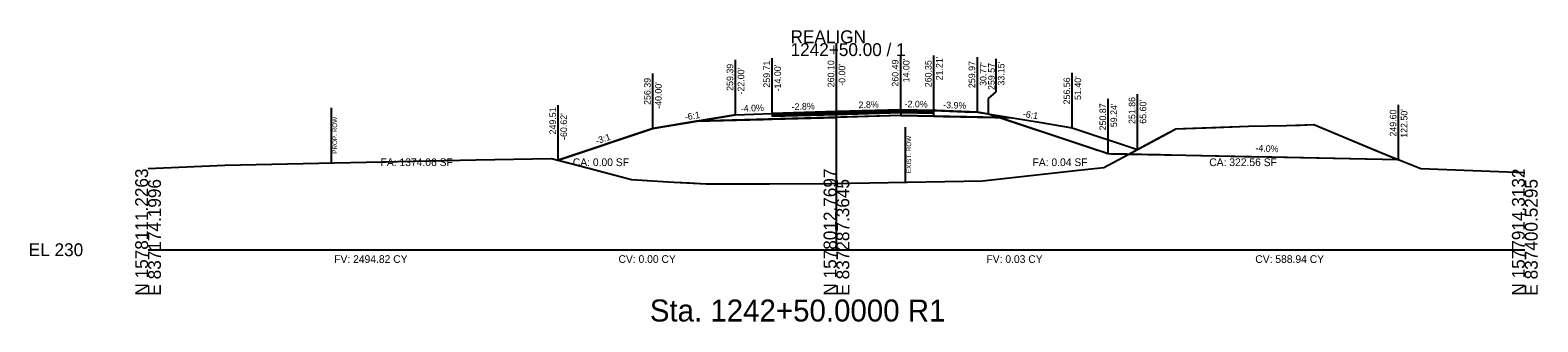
# Model space of a CAD drawing. Extents: x -26 to 6303, y -16 to 9563.
# Drawn here: x 1974.3 to 2302.8, y 2484.3 to 2547.8 of the extents above; entities that cross this region are included whole.
import ezdxf

# ---------------------------------------------------------------- set-up
doc = ezdxf.new("R2010")
doc.units = 0
for name, color, linetype in [('ASPHALT_19MM1', 7, 'Continuous'), ('ASPHALT_9_5MM1', 7, 'Continuous'), ('CONST_DCH', 7, 'Continuous'), ('CONST_LV3', 7, 'Continuous'), ('Draft_XS_Grid', 7, 'Continuous'), ('Draft_XS_Text', 7, 'Continuous'), ('DTM_P_FINISHED_GRADE', 7, 'Continuous'), ('DTM_P_FINISHED_GRADE2', 7, 'Continuous'), ('DTM_TEMP_DROP', 7, 'Continuous'), ('DTM_X_GROUND', 7, 'Continuous'), ('TRANS_EOP_PAVED', 7, 'Continuous'), ('TRANS_PAVED_SHOULDERS', 7, 'Continuous'), ('XS_CELL', 7, 'Continuous'), ('XS_M_SHAPES_EARTHWORK', 7, 'Continuous'), ('XS_P_ASPHALT', 7, 'Continuous'), ('XS_P_GROUND', 7, 'Continuous'), ('XS_P_ROW', 7, 'Continuous'), ('XS_P_SHOULDER', 7, 'Continuous'), ('XS_P_SUBGRADE_GRANULAR', 7, 'Continuous'), ('XS_P_TX_CLEARZONE', 7, 'Continuous'), ('XS_P_TX_FS_BS', 7, 'Continuous'), ('XS_SHEET_EW_TX_AREA', 7, 'Continuous'), ('XS_SHEET_EW_TX_VOLUME', 7, 'Continuous'), ('XS_X_ROW', 7, 'Continuous')]:
    doc.layers.add(name, color=color, linetype=linetype)

msp = doc.modelspace()

# ---------------------------------------------------------------- linework, layer by layer
at = {"layer": 'ASPHALT_19MM1'}
for points in [[(2136, 2529.37), (2136, 2529.1), (2150, 2529.49), (2150, 2529.49), (2164, 2529.89), (2164, 2529.89), (2164, 2530.16), (2164, 2530.16), (2164, 2530.16), (2150, 2529.77), (2150, 2529.77), (2136, 2529.37), (2136, 2529.37)], [(2164, 2530.16), (2164, 2529.89), (2164, 2529.89), (2171.21, 2529.74), (2171.21, 2530.01), (2164, 2530.16), (2164, 2530.16)]]:
    msp.add_lwpolyline(points, dxfattribs=at)
at = {"layer": 'ASPHALT_9_5MM1'}
for points in [[(2136, 2529.71), (2136, 2529.58), (2150, 2529.97), (2150, 2529.97), (2164, 2530.37), (2164, 2530.37), (2164, 2530.49), (2164, 2530.49), (2164, 2530.49), (2150, 2530.1), (2150, 2530.1), (2136, 2529.71), (2136, 2529.71)], [(2164, 2530.49), (2164, 2530.37), (2164, 2530.37), (2171.21, 2530.22), (2171.21, 2530.35), (2164, 2530.49), (2164, 2530.49)]]:
    msp.add_lwpolyline(points, dxfattribs=at)
at = {"layer": 'CONST_LV3'}
for points in [[(2171.21, 2530.35), (2171.21, 2530.35), (2164, 2530.49), (2164, 2530.49), (2150, 2530.1)], [(2164, 2530.49), (2164, 2529.22), (2164, 2529.22), (2171.21, 2529.07), (2171.21, 2530.35), (2164, 2530.49), (2164, 2530.49)], [(2180.71, 2529.97), (2180.71, 2529.97), (2173.67, 2530.25), (2173.67, 2530.25), (2171.78, 2530.32), (2171.78, 2530.32), (2171.21, 2530.35)], [(2119.53, 2527.98), (2110, 2526.39)]]:
    msp.add_lwpolyline(points, dxfattribs=at)
at = {"layer": 'DTM_P_FINISHED_GRADE'}
msp.add_lwpolyline([(2164, 2530.49), (2164, 2530.49), (2171.21, 2530.35)], dxfattribs=at)
at = {"layer": 'DTM_P_FINISHED_GRADE2'}
msp.add_lwpolyline([(2089.38, 2519.51), (2110, 2526.39), (2128, 2529.39), (2136, 2529.71), (2150, 2530.1), (2164, 2530.49), (2171.21, 2530.35), (2177.96, 2530.08), (2180.77, 2529.97)], dxfattribs=at)
at = {"layer": 'DTM_X_GROUND'}
msp.add_lwpolyline([(2000, 2517.66), (2016.7, 2518.4), (2071.45, 2519.57), (2087.88, 2519.91), (2095.75, 2517.83), (2105.32, 2515.27), (2114.55, 2514.74), (2121.62, 2514.35), (2121.89, 2514.36), (2148.98, 2514.4), (2181.82, 2514.99), (2202.74, 2517.35), (2208.26, 2517.94), (2221.97, 2525.27), (2223.99, 2526.35), (2225.61, 2526.4), (2239.79, 2526.89), (2248.07, 2527.1), (2254.04, 2527.25), (2267.88, 2521.46), (2277.32, 2517.67), (2300, 2516.79)], dxfattribs=at)
at = {"layer": 'TRANS_PAVED_SHOULDERS'}
for points in [[(2136, 2529.58), (2136, 2529.37), (2150, 2529.77), (2150, 2529.77), (2164, 2530.16), (2164, 2530.16), (2164, 2530.37), (2164, 2530.37), (2164, 2530.37), (2150, 2529.97), (2150, 2529.97), (2136, 2529.58), (2136, 2529.58)], [(2164, 2530.37), (2164, 2530.16), (2164, 2530.16), (2171.21, 2530.01), (2171.21, 2530.22), (2164, 2530.37), (2164, 2530.37)]]:
    msp.add_lwpolyline(points, dxfattribs=at)
at = {"layer": 'XS_CELL'}
for p, q in [((2150, 2500), (2150, 2545)), ((2000, 2500), (2150, 2500)), ((2150, 2500), (2300, 2500))]:
    msp.add_line(p, q, dxfattribs=at)
at = {"layer": 'XS_M_SHAPES_EARTHWORK'}
msp.add_lwpolyline([(2089.38, 2519.51), (2095.75, 2517.83), (2105.32, 2515.27), (2109.94, 2515.01), (2114.55, 2514.74), (2118.09, 2514.55), (2121.62, 2514.35), (2135.43, 2514.38), (2148.98, 2514.4), (2165.4, 2514.7), (2181.82, 2514.99), (2192.28, 2516.17), (2202.74, 2517.35), (2205.5, 2517.64), (2208.26, 2517.94), (2213.57, 2520.78), (2209.24, 2520.87), (2185.46, 2528.8), (2164, 2529.22), (2119.53, 2527.98), (2110, 2526.39)], close=True, dxfattribs=at)
at = {"layer": 'XS_P_ASPHALT'}
msp.add_lwpolyline([(2164, 2530.49), (2164, 2530.49), (2171.21, 2530.35)], dxfattribs=at)
at = {"layer": 'XS_P_GROUND'}
for points in [[(2209.24, 2520.87), (2209.24, 2520.87), (2209.01, 2520.95), (2208.99, 2520.95), (2208.98, 2520.95), (2208.98, 2520.95), (2208.98, 2520.95), (2208.87, 2520.99), (2208.86, 2521), (2208.41, 2521.15), (2207.04, 2521.6), (2207.04, 2521.6), (2207.02, 2521.61), (2207.01, 2521.61), (2207.01, 2521.61), (2206.89, 2521.65), (2206.89, 2521.65), (2206.47, 2521.79), (2206.47, 2521.79), (2205.24, 2522.2), (2205.24, 2522.2), (2183.15, 2529.57), (2183.15, 2529.57), (2183.15, 2529.57), (2180.82, 2529.95), (2180.82, 2529.95), (2180.71, 2529.97)], [(2180.77, 2529.97), (2194.15, 2527.76), (2201.4, 2526.56), (2215.6, 2521.86)], [(2128, 2529.39), (2110, 2526.39), (2089.38, 2519.51)], [(2240.08, 2520.25), (2239, 2520.27), (2239, 2520.27), (2222.96, 2520.59), (2222.96, 2520.59), (2222.96, 2520.59), (2221.57, 2520.62), (2221.57, 2520.62), (2220.6, 2520.64), (2220.59, 2520.64), (2220.59, 2520.64), (2220.54, 2520.64), (2220.54, 2520.64), (2220.47, 2520.64), (2220.44, 2520.64), (2220.44, 2520.64), (2219.04, 2520.67), (2219.04, 2520.67), (2218.12, 2520.69), (2218.11, 2520.69), (2218.11, 2520.69), (2218.07, 2520.69), (2218.07, 2520.69), (2218.01, 2520.69), (2218.01, 2520.69), (2217.96, 2520.69), (2217.96, 2520.69), (2216.53, 2520.72), (2216.53, 2520.72), (2215.69, 2520.74), (2215.68, 2520.74), (2215.68, 2520.74), (2215.65, 2520.74), (2215.65, 2520.74), (2215.61, 2520.74), (2215.61, 2520.74), (2215.53, 2520.74), (2214.02, 2520.77), (2214.02, 2520.77), (2213.34, 2520.78), (2213.34, 2520.78), (2213.32, 2520.79), (2213.3, 2520.79), (2213.2, 2520.79), (2213.2, 2520.79), (2211.4, 2520.82), (2211.4, 2520.82), (2211.1, 2520.83), (2211.1, 2520.83), (2211.09, 2520.83), (2211.08, 2520.83), (2211.05, 2520.83), (2210.96, 2520.83), (2210.96, 2520.83), (2209.98, 2520.85), (2209.98, 2520.85), (2209.95, 2520.85), (2209.93, 2520.85), (2209.24, 2520.87), (2209.24, 2520.87)], [(2272.5, 2519.6), (2244.84, 2520.15), (2240.47, 2520.24), (2240.08, 2520.25)]]:
    msp.add_lwpolyline(points, dxfattribs=at)
at = {"layer": 'XS_P_ROW'}
msp.add_line((2040, 2518.9), (2040, 2530.9), dxfattribs=at)
at = {"layer": 'XS_P_SHOULDER'}
for points in [[(2128, 2529.39), (2136, 2529.71), (2136, 2529.71)], [(2171.21, 2530.35), (2180.77, 2529.97)]]:
    msp.add_lwpolyline(points, dxfattribs=at)
at = {"layer": 'XS_P_SUBGRADE_GRANULAR'}
for points in [[(2119.53, 2527.98), (2134, 2528.38), (2134, 2528.38), (2136, 2528.44), (2136, 2528.44)], [(2136, 2528.44), (2150, 2528.83), (2150, 2528.83)], [(2164, 2529.22), (2164, 2529.22), (2150, 2528.83)], [(2164, 2529.22), (2164, 2529.22), (2171.21, 2529.07)], [(2171.21, 2529.07), (2173.23, 2529.04), (2188.2, 2528.74)]]:
    msp.add_lwpolyline(points, dxfattribs=at)
at = {"layer": 'XS_P_TX_CLEARZONE'}
for p, q in [((2128, 2529.39), (2128, 2541.39)), ((2136, 2529.71), (2136, 2541.71)), ((2150, 2530.1), (2150, 2542.1)), ((2164, 2530.49), (2164, 2542.49)), ((2171.21, 2530.35), (2171.21, 2542.35)), ((2180.77, 2529.97), (2180.77, 2541.97)), ((2184.78, 2534.37), (2184.78, 2541.57)), ((2110, 2526.39), (2110, 2538.39)), ((2201.4, 2526.56), (2201.4, 2538.56)), ((2183.15, 2532.96), (2184.78, 2534.37)), ((2215.6, 2521.86), (2215.6, 2533.86)), ((2089.38, 2519.51), (2089.38, 2531.51)), ((2183.15, 2529.57), (2183.15, 2532.96)), ((2209.24, 2520.87), (2209.24, 2532.87)), ((2272.5, 2519.6), (2272.5, 2531.6))]:
    msp.add_line(p, q, dxfattribs=at)
at = {"layer": 'XS_P_TX_FS_BS'}
msp.add_lwpolyline([(2213.57, 2520.78), (2215.68, 2521.91), (2219.98, 2524.21), (2223.99, 2526.35), (2232.7, 2526.65), (2239.79, 2526.89), (2248.07, 2527.1), (2251.05, 2527.17), (2254.04, 2527.25), (2272.5, 2519.6), (2219.04, 2520.67)], close=True, dxfattribs=at)
at = {"layer": 'XS_X_ROW'}
msp.add_line((2165.08, 2514.69), (2165.08, 2526.69), dxfattribs=at)

# ---------------------------------------------------------------- texts
at = {"layer": 'CONST_DCH'}
for p in [(2135.92, 2529.59), (2149.92, 2529.98), (2163.92, 2530.37), (2209.17, 2520.75)]:
    msp.add_text('X', height=0.24, dxfattribs=at).set_placement(p)
at = {"layer": 'CONST_LV3'}
for p in [(2109.92, 2526.27), (2201.32, 2526.44)]:
    msp.add_text('X', height=0.24, dxfattribs=at).set_placement(p)
at = {"layer": 'Draft_XS_Grid'}
msp.add_text('-', height=0.0001, dxfattribs=at).set_placement((2000, 2500))
at = {"layer": 'Draft_XS_Text'}
msp.add_text('Sta. 1242+50.0000 R1', height=4.8, dxfattribs=at).set_placement((2109.33, 2484.35))
at = {"layer": 'DTM_TEMP_DROP'}
for p in [(2215.52, 2521.74), (2089.3, 2519.39)]:
    msp.add_text('X', height=0.24, dxfattribs=at).set_placement(p)
at = {"layer": 'TRANS_EOP_PAVED'}
for p in [(2180.64, 2529.85), (2183.07, 2529.45), (2215.52, 2521.74), (2089.3, 2519.39)]:
    msp.add_text('X', height=0.24, dxfattribs=at).set_placement(p)
at = {"layer": 'XS_CELL'}
for s, p in [('REALIGN', (2140, 2545)), ('1242+50.00 / 1', (2140, 2542.2)), ('EL 230', (1974, 2498.6))]:
    msp.add_text(s, height=2.8, dxfattribs=at).set_placement(p)
for s, p in [('N 1578111.2263', (2000, 2490)), ('N 1578012.7697', (2150, 2490)), ('N 1577914.3132', (2300, 2490)), ('E 837174.1996', (2002.8, 2490)), ('E 837287.3645', (2152.8, 2490)), ('E 837400.5295', (2302.8, 2490))]:
    msp.add_text(s, height=2.8, rotation=90, dxfattribs=at).set_placement(p)
at = {"layer": 'XS_P_ASPHALT'}
msp.add_text('X', height=0.24, dxfattribs=at).set_placement((2272.42, 2519.48))
at = {"layer": 'XS_P_ROW'}
msp.add_text('PROP. ROW', height=1, rotation=90, dxfattribs=at).set_placement((2041.2, 2520.9))
at = {"layer": 'XS_P_SUBGRADE_GRANULAR'}
for p in [(2171.14, 2530.23), (2180.7, 2529.85), (2127.92, 2529.27)]:
    msp.add_text('X', height=0.24, dxfattribs=at).set_placement(p)
at = {"layer": 'XS_P_TX_CLEARZONE'}
for s, p in [('259.39', (2127.52, 2534.62)), ('259.71', (2135.52, 2535.32)), ("-14.00'", (2137.92, 2534.5)), ('260.10', (2149.52, 2535.4)), ("-0.00'", (2151.92, 2535.71)), ('260.49', (2163.52, 2535.54)), ("14.00'", (2165.92, 2536.46)), ('260.35', (2170.73, 2535.41)), ("21.21'", (2173.13, 2536.91)), ('259.97', (2180.23, 2535.22)), ("30.77'", (2182.69, 2535.69)), ('259.57', (2184.5, 2534.81)), ("33.15'", (2186.61, 2535.76)), ('256.39', (2109.52, 2531.55)), ("-40.00'", (2111.92, 2530.7)), ("-22.00'", (2129.92, 2533.82)), ('256.56', (2200.92, 2531.66)), ("51.40'", (2203.32, 2532.64)), ('251.86', (2215.12, 2527.39)), ('249.51', (2088.9, 2525.12)), ('250.87', (2208.76, 2526)), ("59.24'", (2211.16, 2526.7)), ("65.60'", (2217.52, 2527.45)), ('249.60', (2272.02, 2524.65)), ("122.50'", (2274.42, 2524.39)), ("-60.62'", (2091.3, 2523.92))]:
    msp.add_text(s, height=1.44, rotation=90, dxfattribs=at).set_placement(p)
at = {"layer": 'XS_P_TX_FS_BS'}
for s, rotation, p in [('-6:1', 9.4642, (2117.08, 2528.17)), ('-4.0%', 2.2906, (2129.18, 2530.04)), ('-2.8%', 1.6039, (2140.25, 2530.43)), ('2.8%', 1.6039, (2154.84, 2530.83)), ('-2.0%', 358.8455, (2164.83, 2531.07)), ('-3.9%', 357.741, (2173.25, 2530.87)), ('-6:1', 350.6434, (2190.55, 2528.95)), ('-3:1', 18.4332, (2097.78, 2522.95)), ('-4.0%', 357.7263, (2241.28, 2521.44))]:
    msp.add_text(s, height=1.44, rotation=rotation, dxfattribs=at).set_placement(p)
at = {"layer": 'XS_SHEET_EW_TX_AREA'}
for s, p in [('FA: 1374.06 SF', (2050.67, 2518.22)), ('CA: 0.00 SF', (2092.56, 2518.22)), ('FA: 0.04 SF', (2192.73, 2518.22)), ('CA: 322.56 SF', (2231.24, 2518.22))]:
    msp.add_text(s, height=1.68, dxfattribs=at).set_placement(p)
at = {"layer": 'XS_SHEET_EW_TX_VOLUME'}
for s, p in [('FV: 2494.82 CY', (2040.56, 2497.12)), ('CV: 0.00 CY', (2102.51, 2497.12)), ('FV: 0.03 CY', (2182.69, 2497.12)), ('CV: 588.94 CY', (2241.27, 2497.12))]:
    msp.add_text(s, height=1.68, dxfattribs=at).set_placement(p)
at = {"layer": 'XS_X_ROW'}
msp.add_text('EXIST. ROW', height=1, rotation=90, dxfattribs=at).set_placement((2166.28, 2516.69))

doc.saveas('drawing.dxf')
